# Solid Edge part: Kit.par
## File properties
Sűrűség: 0,000 kg/m^3
Pontosság: 0,990
Author: ahadarics
Last saved by: psaghy
Revision: 77
Username: ahadarics
Dokumentum tartalom típus: 0
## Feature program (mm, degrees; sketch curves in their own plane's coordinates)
base feature "unnamed BaseFeature 1"
sketch for "Furat_1" plane through (0, 0, 48.5) normal (0, 0, 1) x-axis (0.707107, -0.707107, 0)
  hole centre (0, 62.9325) bore radius 4.188
hole "Furat_1" nominal diameter 10 finite  VBottomAngle = 118 deg; ThreadDepth = 17 mm
sketch for "unnamed Hole 1" plane through (0, 0, 48.5) normal (0, 0, 1) x-axis (0.707107, -0.707107, 0)
  hole centre (-62.9325, 0) bore radius 4.188
hole "unnamed Hole 1" finite
sketch for "unnamed Hole 2" plane through (0, 0, 48.5) normal (0, 0, 1) x-axis (0.707107, -0.707107, 0)
  hole centre (0, -62.9325) bore radius 4.188
hole "unnamed Hole 2" finite
sketch for "unnamed Hole 3" plane through (0, 0, 48.5) normal (0, 0, 1) x-axis (0.707107, -0.707107, 0)
  hole centre (62.9325, 0) bore radius 4.188
hole "unnamed Hole 3" finite
pattern "unnamed Pattern 1" of "Furat_1", "unnamed Hole 1", "unnamed Hole 2", "unnamed Hole 3"
sketch for "Furat_5" plane through (55, -0.0046, 26.9988) normal (1, 0, 0) x-axis (0, 0, -1)
hole "Furat_5" diameter 20.955 finite  ThreadDepth = 25 mm
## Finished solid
Body 1: solid body, 559 faces, 1278 edges, 785 vertices, 8 internal voids.
  Faces by surface: cylinder 177, plane 162, cone 67, sphere 54, torus 53, spline 28, swept 18
  Edges by curve: circle 445, curve on surface 410, line 379, spline 40, ellipse 4
Bounding box of the edges (mm; curved faces can reach further): 110.000 x 110.000 x 78.500, from (-55, -55, 8) to (55, 55, 86.5).
Cylindrical faces by radius (mm): R0.3906 x2, R0.436 x1, R0.4566 x1, R0.5319 x1, R0.6854 x2, R0.701 x1, R0.7273 x1, R0.7952 x1, R0.8489 x1, R0.9223 x1, R1 x31, R1.0003 x1, R1.0017 x8, R1.1393 x1, R1.2532 x1, R1.2992 x1, R1.3173 x1, R1.3418 x1, R1.3734 x1, R1.4839 x1, R1.5702 x1, R1.5902 x3, R1.7026 x2, R1.7139 x2, R1.8341 x1, R2 x12, R2.0009 x12, R2.003 x12, R2.0038 x6, R2.0039 x6, R2.1429 x2, R2.1983 x1, R2.95 x1, R4.188 x8, R5 x4, R5.15 x4, R6 x1, R8 x4, R8.15 x4, R8.5 x2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
Conical faces (half-angle, radius in mm at the cone's reference point): 0.0014 deg R1.001 x6, 1 deg R24.75 x6, 1 deg R44 x6, 1.6538 deg R14.25 x1, 3.5477 deg R15.2454 x1, 5.1705 deg R12.9 x1, 8.3742 deg R12.5032 x1, 13.2989 deg R13.6846 x1, 14.7738 deg R13.2787 x1, 15 deg R25.1732 x1, 25.0169 deg R16.81 x1, 30 deg R6.1443 x1, 30 deg R14.8557 x2, 30 deg R15.1443 x1, 30 deg R26.75 x1, 43.4089 deg R46.25 x1, 45 deg R3.75 x1, 45 deg R3.875 x1, 45 deg R5.3 x8, 45 deg R7.85 x8, 45 deg R10.91 x1, 45 deg R12.65 x2, 45 deg R17.85 x1, 47.9357 deg R39.7887 x6, 47.9357 deg R47.75 x3, 59 deg R4.188 x4
Toroidal faces (ring radius, tube radius in mm): R5.3 r0.3 x4, R5.7 r0.3 x1, R7.95 r0.2 x4, R8.65 r0.5 x4, R11.5 r1 x2, R12.8 r0.3 x1, R12.8088 r0.3 x1, R13.9279 r0.25 x1, R14.7464 r0.5 x1, R15.5 r1 x1, R17.3 r0.2 x1, R23 r3 x1, R23.4827 r1 x1, R26.7154 r2 x6, R28 r0.5 x1, R34.8084 r2 x6, R42.0155 r2 x6, R53 r1 x3, R55.4306 r1 x2, R57 r1 x6
Spherical faces by radius (mm): R1 x18, R2 x36
Planar faces by outward normal: +x 21, +y 11, +z 37, -x 1, -y 10, -z 25, oblique 57
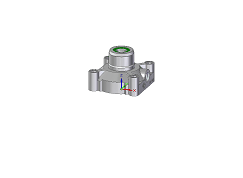
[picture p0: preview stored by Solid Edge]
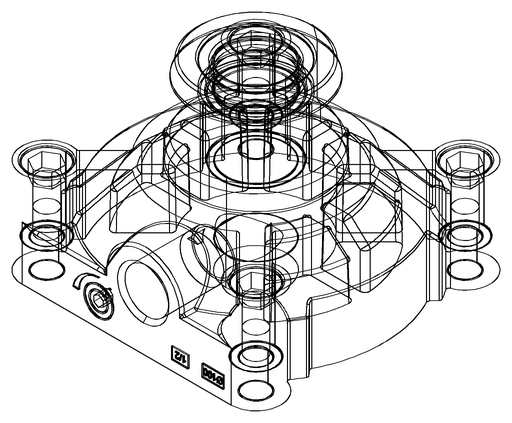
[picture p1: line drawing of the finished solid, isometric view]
